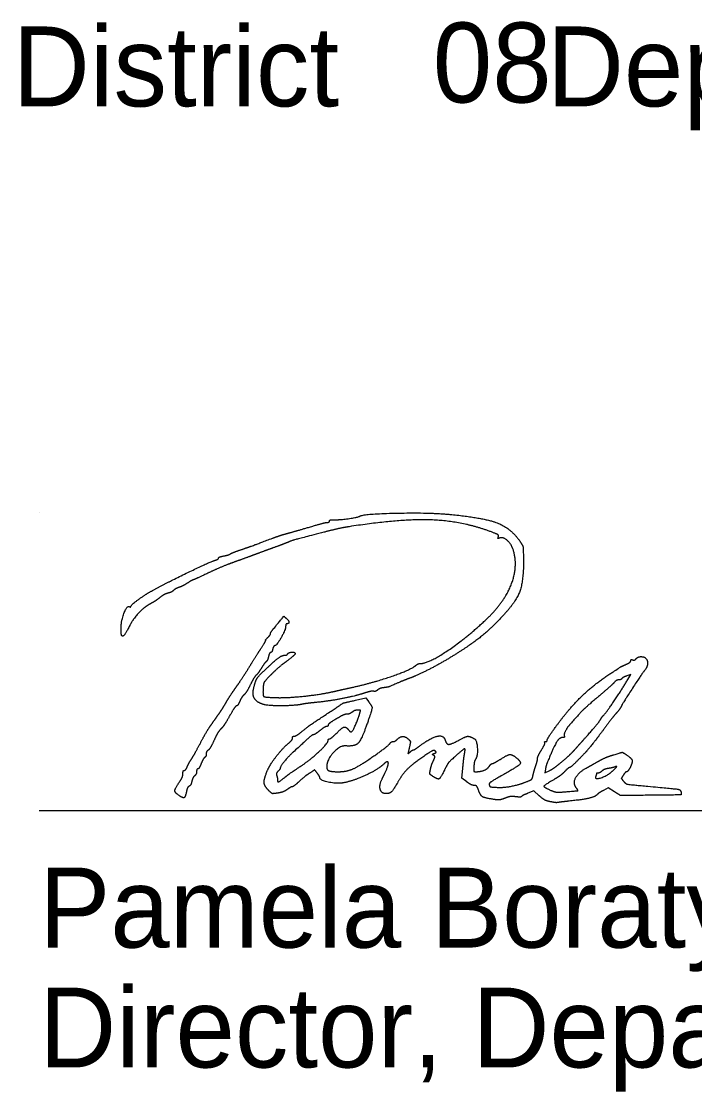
# Model space of a CAD drawing. Extents: x 0 to 34, y -3.9 to 26.2.
# Drawn here: x 24.734 to 25.914, y 4.977 to 6.852 of the extents above; entities that cross this region are included whole.
import ezdxf

# ---------------------------------------------------------------- set-up
doc = ezdxf.new("R2010")
doc.units = 0
doc.layers.add('SH_Data', color=7, linetype='Continuous')
doc.layers.add('SH_Text', color=7, linetype='Continuous')

msp = doc.modelspace()

# ---------------------------------------------------------------- linework, layer by layer
at = {"layer": 'SH_Data'}
for p, q in [((24.7652, 5.9916), (24.7652, 5.9916)), ((24.7652, 5.4694), (28.2652, 5.4694))]:
    msp.add_line(p, q, dxfattribs=at)
at = {"layer": 'SH_Text'}
for points in [[(25.797, 5.6988), (25.8024, 5.7078), (25.795, 5.7052)], [(25.3197, 5.6627), (25.3377, 5.6667), (25.3424, 5.6605)], [(25.5146, 5.5198), (25.5063, 5.5262), (25.5078, 5.5432)], [(25.6526, 5.5418), (25.6516, 5.5354), (25.6602, 5.5398)], [(25.6416, 5.4955), (25.6324, 5.5038), (25.6219, 5.4997)], [(25.7734, 5.5025), (25.7628, 5.5093), (25.7544, 5.5048)]]:
    msp.add_lwpolyline(points, dxfattribs=at)
for points in [[(25.2831, 5.979), (25.2927, 5.9787), (25.3237, 5.9831), (25.3271, 5.9852)], [(25.3271, 5.9852), (25.3339, 5.9894), (25.4509, 5.9917), (25.4853, 5.9883)], [(25.4853, 5.9883), (25.5445, 5.9825), (25.5921, 5.9642), (25.6079, 5.9412)], [(25.1985, 5.9545), (25.2038, 5.9559), (25.2212, 5.9609), (25.2373, 5.9656)], [(25.2373, 5.9656), (25.2534, 5.9704), (25.2683, 5.9743), (25.2703, 5.9743)], [(25.3089, 5.9668), (25.2996, 5.9654), (25.2797, 5.961), (25.2645, 5.9571)], [(25.2703, 5.9743), (25.2724, 5.9743), (25.2741, 5.9754), (25.2741, 5.9768)], [(25.2741, 5.9768), (25.2741, 5.9782), (25.2781, 5.9792), (25.2831, 5.979)], [(25.5578, 5.9576), (25.5072, 5.9766), (25.3992, 5.9806), (25.3089, 5.9668)], [(25.1181, 5.9261), (25.1328, 5.9312), (25.1393, 5.9335), (25.1745, 5.9467)], [(25.1745, 5.9467), (25.1824, 5.9496), (25.1932, 5.9531), (25.1985, 5.9545)], [(25.2645, 5.9571), (25.2135, 5.9439), (25.2092, 5.9427), (25.1985, 5.9383)], [(25.5701, 5.949), (25.5711, 5.9515), (25.5676, 5.9539), (25.5578, 5.9576)], [(25.5725, 5.9469), (25.5699, 5.9459), (25.5692, 5.9465), (25.5701, 5.949)], [(25.5959, 5.927), (25.5926, 5.9367), (25.5782, 5.9491), (25.5725, 5.9469)], [(25.1001, 5.9189), (25.1014, 5.9199), (25.1095, 5.9231), (25.1181, 5.9261)], [(25.1757, 5.9298), (25.1658, 5.9262), (25.1507, 5.9207), (25.1421, 5.9174)], [(25.1985, 5.9383), (25.1958, 5.9372), (25.1856, 5.9334), (25.1757, 5.9298)], [(25.5504, 5.8058), (25.5813, 5.8352), (25.6052, 5.8987), (25.5959, 5.927)], [(25.6079, 5.9412), (25.6128, 5.9339), (25.6137, 5.9296), (25.6141, 5.9117)], [(24.9621, 5.8539), (24.9923, 5.8702), (25.0659, 5.9058), (25.0743, 5.9082)], [(25.0743, 5.9082), (25.0773, 5.9091), (25.0797, 5.9107), (25.0797, 5.9118)], [(25.0797, 5.9118), (25.0797, 5.9129), (25.0837, 5.9145), (25.0887, 5.9155)], [(25.0887, 5.9155), (25.0936, 5.9164), (25.0988, 5.9179), (25.1001, 5.9189)], [(25.1421, 5.9174), (25.1335, 5.9142), (25.1173, 5.9083), (25.1061, 5.9043)], [(25.6141, 5.9117), (25.6148, 5.8709), (25.5987, 5.8312), (25.5693, 5.8013)], [(25.1061, 5.9043), (25.0949, 5.9003), (25.0745, 5.8918), (25.0609, 5.8853)], [(25.035, 5.8735), (25.0345, 5.8735), (25.03, 5.871), (25.025, 5.8679)], [(25.0609, 5.8853), (25.0472, 5.8788), (25.0356, 5.8735), (25.035, 5.8735)], [(24.9261, 5.8273), (24.9261, 5.8294), (24.9515, 5.8482), (24.9621, 5.8539)], [(24.9913, 5.8504), (24.9878, 5.8495), (24.9811, 5.8459), (24.9765, 5.8423)], [(25.001, 5.8552), (24.9992, 5.8534), (24.9949, 5.8512), (24.9913, 5.8504)], [(25.0102, 5.8603), (25.007, 5.8593), (25.0028, 5.857), (25.001, 5.8552)], [(25.025, 5.8679), (25.0201, 5.8647), (25.0134, 5.8614), (25.0102, 5.8603)], [(24.9606, 5.8319), (24.9502, 5.8266), (24.9303, 5.8057), (24.9241, 5.7936)], [(24.9765, 5.8423), (24.9719, 5.8387), (24.9647, 5.834), (24.9606, 5.8319)], [(24.9089, 5.7894), (24.909, 5.8026), (24.9196, 5.8292), (24.9238, 5.8266)], [(24.9238, 5.8266), (24.9251, 5.8259), (24.9261, 5.8262), (24.9261, 5.8273)], [(24.9241, 5.7936), (24.9174, 5.7807), (24.9121, 5.7739), (24.9103, 5.7757)], [(25.1763, 5.7883), (25.1948, 5.8105), (25.1941, 5.8099), (25.1982, 5.8065)], [(25.1997, 5.7967), (25.1984, 5.7967), (25.1973, 5.7944), (25.1973, 5.7916)], [(25.1982, 5.8065), (25.2025, 5.803), (25.2034, 5.7967), (25.1997, 5.7967)], [(25.4337, 5.7271), (25.4478, 5.7271), (25.5159, 5.773), (25.5504, 5.8058)], [(25.5693, 5.8013), (25.5507, 5.7824), (25.5183, 5.7575), (25.4878, 5.7387)], [(24.9103, 5.7757), (24.9095, 5.7765), (24.9089, 5.7827), (24.9089, 5.7894)], [(25.1661, 5.7727), (25.1687, 5.7753), (25.1709, 5.7785), (25.1709, 5.7797)], [(25.1709, 5.7797), (25.1709, 5.7809), (25.1733, 5.7848), (25.1763, 5.7883)], [(25.1973, 5.7916), (25.1973, 5.7861), (25.1814, 5.7583), (25.1782, 5.7583)], [(25.1533, 5.7522), (25.1589, 5.7609), (25.1629, 5.7679), (25.1623, 5.7679)], [(25.1623, 5.7679), (25.1618, 5.7679), (25.1634, 5.7701), (25.1661, 5.7727)], [(25.1782, 5.7583), (25.1771, 5.7583), (25.1755, 5.7556), (25.1747, 5.7523)], [(25.1313, 5.7172), (25.1379, 5.7279), (25.1478, 5.7436), (25.1533, 5.7522)], [(25.1625, 5.7173), (25.1782, 5.732), (25.191, 5.7415), (25.1949, 5.7415)], [(25.1673, 5.7391), (25.1664, 5.7352), (25.1647, 5.7313), (25.1634, 5.7305)], [(25.171, 5.7463), (25.1698, 5.7463), (25.1682, 5.7431), (25.1673, 5.7391)], [(25.1747, 5.7523), (25.1739, 5.749), (25.1722, 5.7463), (25.171, 5.7463)], [(25.1949, 5.7415), (25.1974, 5.7415), (25.2001, 5.7426), (25.2009, 5.7439)], [(25.2141, 5.7443), (25.2141, 5.7432), (25.2073, 5.7373), (25.1991, 5.7311)], [(25.2009, 5.7439), (25.2027, 5.7468), (25.2141, 5.7471), (25.2141, 5.7443)], [(25.4878, 5.7387), (25.4686, 5.7269), (25.4274, 5.7059), (25.4133, 5.7008)], [(25.8118, 5.7356), (25.8134, 5.7375), (25.8171, 5.7391), (25.82, 5.7391)], [(25.82, 5.7391), (25.8295, 5.7391), (25.8332, 5.7231), (25.8258, 5.7141)], [(25.1549, 5.7191), (25.1515, 5.7136), (25.1474, 5.708), (25.1457, 5.7067)], [(25.1634, 5.7305), (25.1621, 5.7297), (25.1583, 5.7246), (25.1549, 5.7191)], [(25.1991, 5.7311), (25.1908, 5.725), (25.1783, 5.7142), (25.1713, 5.707)], [(25.3137, 5.6852), (25.3506, 5.6934), (25.4169, 5.7163), (25.4255, 5.7238)], [(25.4255, 5.7238), (25.4276, 5.7256), (25.4312, 5.7271), (25.4337, 5.7271)], [(25.7653, 5.7087), (25.7843, 5.721), (25.7861, 5.7221), (25.7943, 5.7257)], [(25.7943, 5.7257), (25.7986, 5.7277), (25.8021, 5.7305), (25.8021, 5.732)], [(25.8021, 5.732), (25.8021, 5.7336), (25.8036, 5.7342), (25.8055, 5.7335)], [(25.8055, 5.7335), (25.8074, 5.7328), (25.8102, 5.7337), (25.8118, 5.7356)], [(25.1095, 5.6843), (25.1149, 5.6918), (25.1247, 5.7066), (25.1313, 5.7172)], [(25.1457, 5.7067), (25.1441, 5.7053), (25.1394, 5.6977), (25.1354, 5.6897)], [(25.1411, 5.6827), (25.1439, 5.6958), (25.1501, 5.7057), (25.1625, 5.7173)], [(25.1713, 5.707), (25.1606, 5.6961), (25.1584, 5.6924), (25.1579, 5.6842)], [(25.4133, 5.7008), (25.4087, 5.6991), (25.4016, 5.6963), (25.3976, 5.6946)], [(25.6707, 5.6162), (25.6929, 5.647), (25.738, 5.691), (25.7653, 5.7087)], [(25.7863, 5.7005), (25.7856, 5.6993), (25.7832, 5.6983), (25.781, 5.6983)], [(25.8258, 5.7141), (25.8216, 5.7091), (25.7888, 5.6586), (25.7856, 5.6524)], [(25.795, 5.7052), (25.791, 5.7038), (25.7871, 5.7017), (25.7863, 5.7005)], [(25.0928, 5.6587), (25.0966, 5.6653), (25.1042, 5.6768), (25.1095, 5.6843)], [(25.1354, 5.6897), (25.1314, 5.6817), (25.1263, 5.6737), (25.1241, 5.672)], [(25.1565, 5.6559), (25.146, 5.6598), (25.1389, 5.6722), (25.1411, 5.6827)], [(25.1579, 5.6842), (25.157, 5.6707), (25.1611, 5.6678), (25.1817, 5.6673)], [(25.2801, 5.6777), (25.288, 5.6795), (25.3031, 5.6828), (25.3137, 5.6852)], [(25.3691, 5.6847), (25.3652, 5.6842), (25.3604, 5.6824), (25.3583, 5.6806)], [(25.3976, 5.6946), (25.3806, 5.6871), (25.3757, 5.6854), (25.3691, 5.6847)], [(25.7722, 5.6929), (25.7695, 5.6899), (25.757, 5.6789), (25.7445, 5.6683)], [(25.7542, 5.6359), (25.757, 5.6379), (25.7852, 5.6794), (25.797, 5.6988)], [(25.781, 5.6983), (25.7788, 5.6983), (25.7748, 5.6959), (25.7722, 5.6929)], [(25.1241, 5.672), (25.122, 5.6702), (25.1187, 5.6651), (25.1169, 5.6607)], [(25.1817, 5.6673), (25.2009, 5.6668), (25.2588, 5.6729), (25.2801, 5.6777)], [(25.3335, 5.6747), (25.317, 5.6694), (25.2719, 5.6609), (25.2481, 5.6586)], [(25.2657, 5.6362), (25.2973, 5.6573), (25.2987, 5.658), (25.3197, 5.6627)], [(25.3515, 5.6784), (25.3498, 5.679), (25.3417, 5.6773), (25.3335, 5.6747)], [(25.3583, 5.6806), (25.3562, 5.6788), (25.3531, 5.6778), (25.3515, 5.6784)], [(25.7445, 5.6683), (25.7249, 5.6518), (25.7132, 5.6404), (25.6965, 5.6215)], [(25.0798, 5.6381), (25.0831, 5.6428), (25.089, 5.6521), (25.0928, 5.6587)], [(25.1112, 5.6527), (25.1099, 5.6527), (25.1045, 5.6448), (25.0991, 5.6351)], [(25.1169, 5.6607), (25.115, 5.6563), (25.1125, 5.6527), (25.1112, 5.6527)], [(25.2277, 5.656), (25.214, 5.653), (25.1645, 5.6529), (25.1565, 5.6559)], [(25.2481, 5.6586), (25.2398, 5.6578), (25.2306, 5.6566), (25.2277, 5.656)], [(25.3237, 5.6454), (25.3208, 5.6454), (25.3164, 5.6438), (25.3138, 5.6418)], [(25.327, 5.6389), (25.3287, 5.6447), (25.3283, 5.6455), (25.3237, 5.6454)], [(25.3424, 5.6605), (25.349, 5.6518), (25.3488, 5.6469), (25.3411, 5.6243)], [(25.7856, 5.6524), (25.7839, 5.649), (25.78, 5.6435), (25.777, 5.6403)], [(25.0662, 5.6189), (25.0703, 5.6247), (25.0764, 5.6333), (25.0798, 5.6381)], [(25.0991, 5.6351), (25.0938, 5.6255), (25.0871, 5.6155), (25.0843, 5.6129)], [(25.2265, 5.6083), (25.2402, 5.6194), (25.2382, 5.618), (25.2657, 5.6362)], [(25.2954, 5.6352), (25.2809, 5.6272), (25.2717, 5.6208), (25.2717, 5.6189)], [(25.3051, 5.6383), (25.3029, 5.6383), (25.2985, 5.6369), (25.2954, 5.6352)], [(25.3138, 5.6418), (25.3113, 5.6399), (25.3073, 5.6383), (25.3051, 5.6383)], [(25.3123, 5.6071), (25.3141, 5.6071), (25.3239, 5.6282), (25.327, 5.6389)], [(25.719, 5.5929), (25.7343, 5.6101), (25.7479, 5.6264), (25.7503, 5.6308)], [(25.7503, 5.6308), (25.7515, 5.6329), (25.7533, 5.6352), (25.7542, 5.6359)], [(25.777, 5.6403), (25.774, 5.6371), (25.7651, 5.6257), (25.7572, 5.6151)], [(25.0473, 5.5867), (25.0536, 5.5986), (25.0621, 5.6131), (25.0662, 5.6189)], [(25.0843, 5.6129), (25.0814, 5.6104), (25.0759, 5.6013), (25.072, 5.5927)], [(25.2127, 5.5999), (25.2145, 5.5999), (25.2207, 5.6037), (25.2265, 5.6083)], [(25.2573, 5.6095), (25.2523, 5.6055), (25.2473, 5.6023), (25.2461, 5.6023)], [(25.269, 5.6167), (25.2676, 5.6167), (25.2623, 5.6135), (25.2573, 5.6095)], [(25.2717, 5.6189), (25.2717, 5.6177), (25.2705, 5.6167), (25.269, 5.6167)], [(25.2861, 5.6047), (25.2962, 5.6148), (25.3028, 5.6166), (25.3077, 5.6107)], [(25.3411, 5.6243), (25.3308, 5.5945), (25.3188, 5.5814), (25.3029, 5.5827)], [(25.3077, 5.6107), (25.3093, 5.6087), (25.3114, 5.6071), (25.3123, 5.6071)], [(25.6557, 5.5929), (25.6557, 5.5943), (25.6624, 5.6048), (25.6707, 5.6162)], [(25.6965, 5.6215), (25.6906, 5.6149), (25.6844, 5.6021), (25.6858, 5.5997)], [(25.7572, 5.6151), (25.7493, 5.6044), (25.7416, 5.5942), (25.7402, 5.5924)], [(25.072, 5.5927), (25.068, 5.5841), (25.0633, 5.5762), (25.0615, 5.5752)], [(25.1658, 5.5404), (25.1703, 5.5509), (25.1935, 5.5803), (25.2039, 5.5887)], [(25.2039, 5.5887), (25.2068, 5.5911), (25.2093, 5.5946), (25.2093, 5.5965)], [(25.2093, 5.5965), (25.2093, 5.5984), (25.2108, 5.5999), (25.2127, 5.5999)], [(25.2461, 5.6023), (25.2442, 5.6023), (25.2358, 5.595), (25.2105, 5.5718)], [(25.2256, 5.5485), (25.2412, 5.5589), (25.2717, 5.5877), (25.2717, 5.592)], [(25.2717, 5.592), (25.2717, 5.5937), (25.2728, 5.5951), (25.2741, 5.5951)], [(25.2741, 5.5951), (25.2754, 5.5951), (25.2808, 5.5994), (25.2861, 5.6047)], [(25.3377, 5.5554), (25.3563, 5.5678), (25.3787, 5.5845), (25.3804, 5.5872)], [(25.3804, 5.5872), (25.3815, 5.5889), (25.3838, 5.5903), (25.3856, 5.5903)], [(25.3856, 5.5903), (25.3875, 5.5903), (25.3907, 5.5921), (25.3928, 5.5942)], [(25.3928, 5.5942), (25.3978, 5.5992), (25.4078, 5.5992), (25.4127, 5.5943)], [(25.4127, 5.5943), (25.4159, 5.5911), (25.4161, 5.5886), (25.414, 5.5795)], [(25.4308, 5.5816), (25.4511, 5.5968), (25.4738, 5.6024), (25.4768, 5.593)], [(25.4768, 5.593), (25.4792, 5.5854), (25.4873, 5.5853), (25.5006, 5.5926)], [(25.5006, 5.5926), (25.5125, 5.5992), (25.5198, 5.5999), (25.528, 5.5953)], [(25.528, 5.5953), (25.5324, 5.5929), (25.5341, 5.5649), (25.5302, 5.5597)], [(25.6459, 5.576), (25.6498, 5.5823), (25.6523, 5.5881), (25.6515, 5.5889)], [(25.6515, 5.5889), (25.6507, 5.5897), (25.6513, 5.5903), (25.6529, 5.5903)], [(25.6529, 5.5903), (25.6544, 5.5903), (25.6557, 5.5915), (25.6557, 5.5929)], [(25.6835, 5.5975), (25.6772, 5.5975), (25.6677, 5.5823), (25.6556, 5.5531)], [(25.6858, 5.5997), (25.6866, 5.5985), (25.6855, 5.5975), (25.6835, 5.5975)], [(25.7034, 5.5755), (25.7065, 5.579), (25.7135, 5.5869), (25.719, 5.5929)], [(25.7402, 5.5924), (25.7269, 5.576), (25.7224, 5.5708), (25.7105, 5.5587)], [(25.0319, 5.5591), (25.0341, 5.5624), (25.0411, 5.5748), (25.0473, 5.5867)], [(25.0581, 5.5687), (25.0581, 5.5662), (25.057, 5.5635), (25.0556, 5.5626)], [(25.0615, 5.5752), (25.0596, 5.5741), (25.0581, 5.5712), (25.0581, 5.5687)], [(25.2105, 5.5718), (25.2014, 5.5634), (25.1877, 5.5463), (25.1877, 5.5434)], [(25.3029, 5.5827), (25.2925, 5.5836), (25.2693, 5.5582), (25.2693, 5.546)], [(25.414, 5.5795), (25.4117, 5.5692), (25.4118, 5.5688), (25.4156, 5.5722)], [(25.4156, 5.5722), (25.4178, 5.5742), (25.4205, 5.5759), (25.4214, 5.5759)], [(25.4214, 5.5759), (25.4224, 5.5759), (25.4266, 5.5785), (25.4308, 5.5816)], [(25.4595, 5.5738), (25.4577, 5.5756), (25.4518, 5.5729), (25.4393, 5.5644)], [(25.4567, 5.5662), (25.4545, 5.5676), (25.4548, 5.5685), (25.4579, 5.5696)], [(25.4579, 5.5696), (25.4609, 5.5708), (25.4613, 5.572), (25.4595, 5.5738)], [(25.5006, 5.5698), (25.4847, 5.5557), (25.481, 5.5513), (25.4755, 5.54)], [(25.5107, 5.5681), (25.5125, 5.5775), (25.5099, 5.578), (25.5006, 5.5698)], [(25.6389, 5.5612), (25.6389, 5.5631), (25.6421, 5.5697), (25.6459, 5.576)], [(25.6833, 5.5566), (25.6912, 5.5635), (25.7003, 5.5719), (25.7034, 5.5755)], [(25.7726, 5.5673), (25.7866, 5.5715), (25.7878, 5.5716), (25.7937, 5.5677)], [(25.025, 5.5465), (25.0266, 5.5501), (25.0297, 5.5558), (25.0319, 5.5591)], [(25.0493, 5.5517), (25.0473, 5.5465), (25.0446, 5.5423), (25.0434, 5.5423)], [(25.0556, 5.5626), (25.0542, 5.5618), (25.0514, 5.5569), (25.0493, 5.5517)], [(25.2892, 5.5375), (25.3023, 5.5375), (25.3214, 5.5446), (25.3377, 5.5554)], [(25.3697, 5.5513), (25.3601, 5.5421), (25.3213, 5.5233), (25.3029, 5.5189)], [(25.3667, 5.5255), (25.3708, 5.5332), (25.3773, 5.5495), (25.3773, 5.5522)], [(25.3773, 5.5522), (25.3773, 5.5553), (25.3733, 5.5548), (25.3697, 5.5513)], [(25.4393, 5.5644), (25.4196, 5.5509), (25.4024, 5.5339), (25.3941, 5.5195)], [(25.4509, 5.5407), (25.4517, 5.5449), (25.454, 5.5519), (25.456, 5.5563)], [(25.456, 5.5563), (25.4588, 5.5626), (25.459, 5.5648), (25.4567, 5.5662)], [(25.5078, 5.5432), (25.5086, 5.5526), (25.5099, 5.5638), (25.5107, 5.5681)], [(25.5302, 5.5597), (25.5289, 5.558), (25.5276, 5.5524), (25.5272, 5.5471)], [(25.5541, 5.547), (25.556, 5.5497), (25.5585, 5.5519), (25.5597, 5.5519)], [(25.5597, 5.5519), (25.5609, 5.5519), (25.567, 5.5551), (25.5733, 5.5591)], [(25.6015, 5.5621), (25.6112, 5.5545), (25.6043, 5.5465), (25.5727, 5.5288)], [(25.5733, 5.5591), (25.5862, 5.5673), (25.5938, 5.5681), (25.6015, 5.5621)], [(25.6354, 5.5471), (25.6373, 5.553), (25.6389, 5.5594), (25.6389, 5.5612)], [(25.6556, 5.5531), (25.6545, 5.5505), (25.6532, 5.5454), (25.6526, 5.5418)], [(25.6602, 5.5398), (25.665, 5.5422), (25.6754, 5.5498), (25.6833, 5.5566)], [(25.7105, 5.5587), (25.703, 5.551), (25.6959, 5.5447), (25.6949, 5.5447)], [(25.7237, 5.5436), (25.7266, 5.5452), (25.7354, 5.5501), (25.7433, 5.5547)], [(25.7433, 5.5547), (25.7512, 5.5592), (25.7644, 5.5649), (25.7726, 5.5673)], [(25.7937, 5.5677), (25.8033, 5.5614), (25.8057, 5.554), (25.8011, 5.545)], [(25.0115, 5.52), (25.0147, 5.5247), (25.0173, 5.5311), (25.0173, 5.5342)], [(25.0173, 5.5342), (25.0173, 5.5374), (25.0184, 5.5399), (25.0197, 5.5399)], [(25.0197, 5.5399), (25.0211, 5.5399), (25.0235, 5.5429), (25.025, 5.5465)], [(25.0413, 5.5378), (25.0413, 5.5353), (25.0397, 5.532), (25.0378, 5.5304)], [(25.0434, 5.5423), (25.0422, 5.5423), (25.0413, 5.5403), (25.0413, 5.5378)], [(25.1675, 5.5047), (25.1598, 5.5123), (25.1593, 5.5252), (25.1658, 5.5404)], [(25.1839, 5.5382), (25.1819, 5.5362), (25.1808, 5.5329), (25.1815, 5.531)], [(25.1815, 5.531), (25.1823, 5.5291), (25.1829, 5.526), (25.1829, 5.5241)], [(25.1877, 5.5434), (25.1877, 5.5426), (25.186, 5.5403), (25.1839, 5.5382)], [(25.1941, 5.5262), (25.2016, 5.5323), (25.2069, 5.536), (25.2256, 5.5485)], [(25.2414, 5.5363), (25.2332, 5.5309), (25.2306, 5.5289), (25.2194, 5.5189)], [(25.2527, 5.5349), (25.2482, 5.5408), (25.2482, 5.5408), (25.2414, 5.5363)], [(25.2572, 5.5276), (25.2572, 5.5284), (25.2552, 5.5317), (25.2527, 5.5349)], [(25.2693, 5.546), (25.2693, 5.5408), (25.2771, 5.5375), (25.2892, 5.5375)], [(25.4555, 5.5292), (25.4505, 5.5324), (25.4497, 5.5344), (25.4509, 5.5407)], [(25.4755, 5.54), (25.4688, 5.5263), (25.464, 5.5236), (25.4555, 5.5292)], [(25.5272, 5.5471), (25.5267, 5.5395), (25.5274, 5.5375), (25.5306, 5.5375)], [(25.5306, 5.5375), (25.5389, 5.5375), (25.5509, 5.5423), (25.5541, 5.547)], [(25.6306, 5.53), (25.6313, 5.5335), (25.6334, 5.5412), (25.6354, 5.5471)], [(25.6863, 5.5377), (25.6827, 5.5339), (25.6746, 5.5278), (25.6683, 5.5242)], [(25.6949, 5.5447), (25.6938, 5.5447), (25.6899, 5.5416), (25.6863, 5.5377)], [(25.7067, 5.5092), (25.7006, 5.5167), (25.7104, 5.5364), (25.7237, 5.5436)], [(25.7407, 5.5294), (25.7381, 5.5228), (25.7636, 5.5318), (25.7721, 5.5404)], [(25.7421, 5.5341), (25.7421, 5.5335), (25.7414, 5.5314), (25.7407, 5.5294)], [(25.7449, 5.5351), (25.7434, 5.5351), (25.7421, 5.5347), (25.7421, 5.5341)], [(25.7517, 5.5387), (25.7495, 5.5367), (25.7464, 5.5351), (25.7449, 5.5351)], [(25.7627, 5.5432), (25.7588, 5.5427), (25.7539, 5.5407), (25.7517, 5.5387)], [(25.7745, 5.546), (25.7718, 5.545), (25.7665, 5.5437), (25.7627, 5.5432)], [(25.7721, 5.5404), (25.7776, 5.546), (25.7781, 5.5473), (25.7745, 5.546)], [(25.7892, 5.5317), (25.7857, 5.5263), (25.7857, 5.5255), (25.7896, 5.5207)], [(25.7951, 5.5375), (25.794, 5.5375), (25.7913, 5.5349), (25.7892, 5.5317)], [(25.8011, 5.545), (25.7989, 5.5409), (25.7962, 5.5375), (25.7951, 5.5375)], [(25.0098, 5.4963), (25.0028, 5.5012), (25.0033, 5.5079), (25.0115, 5.52)], [(25.0281, 5.512), (25.0264, 5.5113), (25.0243, 5.5072), (25.0235, 5.5028)], [(25.0328, 5.5204), (25.0319, 5.5164), (25.0298, 5.5126), (25.0281, 5.512)], [(25.0378, 5.5304), (25.0359, 5.5289), (25.0337, 5.5243), (25.0328, 5.5204)], [(25.1829, 5.5241), (25.1829, 5.5192), (25.1863, 5.5199), (25.1941, 5.5262)], [(25.2194, 5.5189), (25.2146, 5.5146), (25.2098, 5.5111), (25.2087, 5.5111)], [(25.3029, 5.5189), (25.29, 5.5158), (25.2574, 5.522), (25.2572, 5.5276)], [(25.3734, 5.4991), (25.365, 5.4991), (25.361, 5.5149), (25.3667, 5.5255)], [(25.3941, 5.5195), (25.3859, 5.5054), (25.3795, 5.4991), (25.3734, 5.4991)], [(25.5276, 5.5135), (25.5251, 5.5135), (25.5192, 5.5164), (25.5146, 5.5198)], [(25.5351, 5.5057), (25.5333, 5.5109), (25.5307, 5.5135), (25.5276, 5.5135)], [(25.5727, 5.5288), (25.5595, 5.5214), (25.5533, 5.5166), (25.5541, 5.5144)], [(25.5541, 5.5144), (25.5554, 5.511), (25.5562, 5.5108), (25.5681, 5.5101)], [(25.5681, 5.5101), (25.5786, 5.5095), (25.6048, 5.5143), (25.6179, 5.5194)], [(25.6179, 5.5194), (25.6267, 5.5228), (25.6297, 5.5252), (25.6306, 5.53)], [(25.6683, 5.5242), (25.6504, 5.5137), (25.6493, 5.5105), (25.6623, 5.5049)], [(25.7896, 5.5207), (25.7932, 5.5162), (25.7982, 5.5152), (25.8321, 5.5121)], [(25.8321, 5.5121), (25.8812, 5.5075), (25.8894, 5.506), (25.8904, 5.5012)], [(25.0235, 5.5028), (25.0216, 5.493), (25.0174, 5.491), (25.0098, 5.4963)], [(25.1837, 5.5001), (25.175, 5.4988), (25.1728, 5.4994), (25.1675, 5.5047)], [(25.2002, 5.5064), (25.1966, 5.5038), (25.1892, 5.5009), (25.1837, 5.5001)], [(25.2087, 5.5111), (25.2076, 5.5111), (25.2038, 5.509), (25.2002, 5.5064)], [(25.5605, 5.4892), (25.5455, 5.4916), (25.5386, 5.496), (25.5351, 5.5057)], [(25.6005, 5.4937), (25.5947, 5.4944), (25.5874, 5.4934), (25.5816, 5.4911)], [(25.6106, 5.494), (25.6102, 5.4931), (25.6056, 5.493), (25.6005, 5.4937)], [(25.6219, 5.4997), (25.616, 5.4975), (25.611, 5.4949), (25.6106, 5.494)], [(25.6562, 5.4861), (25.6532, 5.4867), (25.6466, 5.491), (25.6416, 5.4955)], [(25.6623, 5.5049), (25.6691, 5.502), (25.6756, 5.5014), (25.6891, 5.5025)], [(25.6891, 5.5025), (25.7086, 5.504), (25.7104, 5.5047), (25.7067, 5.5092)], [(25.7427, 5.497), (25.739, 5.4932), (25.7175, 5.4884), (25.6941, 5.486)], [(25.7544, 5.5048), (25.7498, 5.5023), (25.7445, 5.4988), (25.7427, 5.497)], [(25.8201, 5.4961), (25.7844, 5.4957), (25.784, 5.4958), (25.7734, 5.5025)], [(25.8904, 5.5012), (25.8912, 5.497), (25.8892, 5.4968), (25.8201, 5.4961)], [(25.5816, 5.4911), (25.5746, 5.4883), (25.5691, 5.4878), (25.5605, 5.4892)], [(25.6665, 5.4839), (25.6638, 5.4844), (25.6592, 5.4854), (25.6562, 5.4861)], [(25.6749, 5.4836), (25.6729, 5.4832), (25.6691, 5.4834), (25.6665, 5.4839)], [(25.6941, 5.486), (25.6855, 5.4851), (25.6769, 5.484), (25.6749, 5.4836)]]:
    msp.add_open_spline(points, degree=2, dxfattribs=at)

# ---------------------------------------------------------------- texts
for s, p in [('District       Deputy Director', (24.7189, 6.7031)), ('              08', (24.727, 6.7099)), ('Pamela Boratyn', (24.7652, 5.2294)), ('Director, Department of Transportation', (24.7652, 5.0194))]:
    msp.add_text(s, height=0.14, dxfattribs=at).set_placement(p)

doc.saveas('drawing.dxf')
